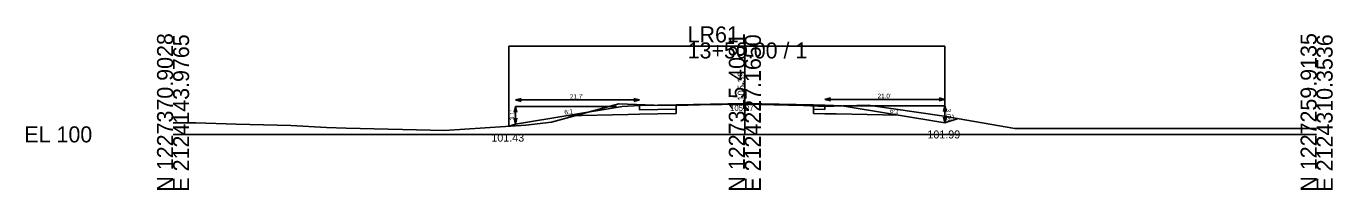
# Model space of a CAD drawing. Extents: x 2126751 to 2128979, y 1225108 to 1234639.
# Drawn here: x 2127750.9 to 2127979.4, y 1228607.5 to 1228636.1 of the extents above; entities that cross this region are included whole.
import ezdxf

# ---------------------------------------------------------------- set-up
doc = ezdxf.new("R2010")
doc.units = 0
for name, color, linetype in [('XS_CELL', 7, 'Continuous'), ('XS_M_DITCH', 7, 'Continuous'), ('XS_P_FINISHED_GRADE', 7, 'Continuous'), ('XS_P_FINISHED_GRADE_ELEV_TX', 7, 'Continuous'), ('XS_P_SUBGRADE_GRANULAR', 7, 'Continuous'), ('XS_P_SUBGRADE_LEVELING', 7, 'Continuous'), ('XS_P_SUBGRADE_PAVEMENT', 7, 'Continuous'), ('XS_P_TX_CLEARZONE', 7, 'Continuous'), ('XS_P_TX_DCH', 7, 'Continuous'), ('XS_P_TX_FS_BS', 7, 'Continuous'), ('XS_X_GROUND', 7, 'Continuous'), ('XS_X_GROUND_TX', 7, 'Continuous')]:
    doc.layers.add(name, color=color, linetype=linetype)

msp = doc.modelspace()

# ---------------------------------------------------------------- linework, layer by layer
at = {"layer": 'XS_CELL'}
for p, q in [((2127876.61, 1228617.21), (2127876.61, 1228633.28)), ((2127776.61, 1228617.21), (2127876.61, 1228617.21)), ((2127876.61, 1228617.21), (2127976.61, 1228617.21))]:
    msp.add_line(p, q, dxfattribs=at)
at = {"layer": 'XS_M_DITCH'}
for p, q in [((2127835.35, 1228618.64), (2127835.35, 1228632.6)), ((2127835.35, 1228632.6), (2127911.61, 1228632.6)), ((2127911.61, 1228632.6), (2127911.61, 1228619.2))]:
    msp.add_line(p, q, dxfattribs=at)
at = {"layer": 'XS_P_FINISHED_GRADE'}
for p, q in [((2127855.16, 1228622.11), (2127836.51, 1228619.02)), ((2127858.18, 1228622.23), (2127855.16, 1228622.11)), ((2127864.61, 1228622.36), (2127858.18, 1228622.23)), ((2127864.61, 1228622.36), (2127876.61, 1228622.6)), ((2127876.61, 1228622.6), (2127888.61, 1228622.36)), ((2127888.61, 1228622.36), (2127890.61, 1228622.32)), ((2127890.61, 1228622.32), (2127893.61, 1228622.2)), ((2127893.61, 1228622.2), (2127911.61, 1228619.2)), ((2127836.51, 1228619.02), (2127835.35, 1228618.64)), ((2127911.61, 1228619.2), (2127913.91, 1228619.97))]:
    msp.add_line(p, q, dxfattribs=at)
at = {"layer": 'XS_P_SUBGRADE_GRANULAR'}
for p, q in [((2127864.61, 1228620.86), (2127864.61, 1228621.61)), ((2127888.61, 1228620.86), (2127888.61, 1228621.61)), ((2127856.18, 1228620.69), (2127845.28, 1228620.47)), ((2127858.18, 1228620.73), (2127856.18, 1228620.69)), ((2127864.61, 1228620.86), (2127858.18, 1228620.73)), ((2127888.61, 1228620.86), (2127890.61, 1228620.82)), ((2127890.61, 1228620.82), (2127892.61, 1228620.78)), ((2127892.61, 1228620.78), (2127903.43, 1228620.56))]:
    msp.add_line(p, q, dxfattribs=at)
at = {"layer": 'XS_P_SUBGRADE_LEVELING'}
for p, q in [((2127864.61, 1228622.28), (2127868.79, 1228622.36)), ((2127864.61, 1228622.36), (2127864.61, 1228622.28)), ((2127868.79, 1228622.36), (2127876.46, 1228622.48)), ((2127876.46, 1228622.48), (2127886.84, 1228622.25)), ((2127886.84, 1228622.25), (2127888.61, 1228622.18)), ((2127888.61, 1228622.36), (2127888.61, 1228622.18))]:
    msp.add_line(p, q, dxfattribs=at)
at = {"layer": 'XS_P_SUBGRADE_PAVEMENT'}
for p, q in [((2127858.18, 1228621.48), (2127858.18, 1228622.23)), ((2127864.61, 1228621.61), (2127858.18, 1228621.48)), ((2127864.61, 1228621.61), (2127864.61, 1228622.28)), ((2127888.61, 1228621.61), (2127888.61, 1228622.18)), ((2127888.61, 1228621.61), (2127890.61, 1228621.57)), ((2127890.61, 1228621.57), (2127890.61, 1228622.32))]:
    msp.add_line(p, q, dxfattribs=at)
at = {"layer": 'XS_P_TX_CLEARZONE'}
for p, q in [((2127836.51, 1228623.23), (2127837.51, 1228623.48)), ((2127858.18, 1228623.23), (2127857.17, 1228623.48)), ((2127890.61, 1228623.32), (2127891.61, 1228623.57)), ((2127890.61, 1228623.32), (2127891.61, 1228623.07)), ((2127890.61, 1228623.32), (2127911.61, 1228623.32)), ((2127911.61, 1228623.32), (2127910.61, 1228623.57)), ((2127911.61, 1228623.32), (2127910.61, 1228623.07)), ((2127836.51, 1228622.11), (2127836.26, 1228621.11)), ((2127836.51, 1228623.23), (2127837.51, 1228622.98)), ((2127858.18, 1228623.23), (2127836.51, 1228623.23)), ((2127836.51, 1228622.11), (2127836.76, 1228621.11)), ((2127836.51, 1228622.11), (2127836.51, 1228619.02)), ((2127854.16, 1228622.11), (2127836.51, 1228622.11)), ((2127858.18, 1228623.23), (2127857.17, 1228622.98)), ((2127894.61, 1228622.2), (2127911.61, 1228622.2)), ((2127911.61, 1228622.2), (2127911.36, 1228621.2)), ((2127911.61, 1228622.2), (2127911.61, 1228619.2)), ((2127911.61, 1228622.2), (2127911.86, 1228621.2)), ((2127836.51, 1228619.02), (2127836.26, 1228620.02)), ((2127836.51, 1228619.02), (2127836.76, 1228620.02)), ((2127911.61, 1228619.2), (2127911.36, 1228620.2)), ((2127911.61, 1228619.2), (2127911.86, 1228620.2))]:
    msp.add_line(p, q, dxfattribs=at)
at = {"layer": 'XS_X_GROUND'}
for p, q in [((2127842.77, 1228619.32), (2127853.71, 1228622.34)), ((2127853.71, 1228622.34), (2127854.59, 1228622.57)), ((2127854.59, 1228622.57), (2127862.25, 1228622.23)), ((2127862.25, 1228622.23), (2127868.79, 1228622.36)), ((2127868.79, 1228622.36), (2127876.46, 1228622.48)), ((2127876.46, 1228622.48), (2127886.84, 1228622.25)), ((2127886.84, 1228622.25), (2127890.59, 1228622.1)), ((2127890.59, 1228622.1), (2127893.82, 1228622.2)), ((2127893.82, 1228622.2), (2127894.24, 1228622.21)), ((2127894.24, 1228622.21), (2127898.15, 1228622.3)), ((2127898.15, 1228622.3), (2127911.08, 1228620.45)), ((2127776.61, 1228619.25), (2127780.6, 1228619.24)), ((2127780.6, 1228619.24), (2127787.67, 1228618.99)), ((2127787.67, 1228618.99), (2127797.19, 1228618.76)), ((2127797.19, 1228618.76), (2127803.44, 1228618.44)), ((2127824.1, 1228617.88), (2127838.33, 1228618.84)), ((2127838.33, 1228618.84), (2127842.77, 1228619.32)), ((2127911.08, 1228620.45), (2127923.84, 1228618.26)), ((2127803.44, 1228618.44), (2127806.87, 1228618.28)), ((2127806.87, 1228618.28), (2127824.1, 1228617.88)), ((2127923.84, 1228618.26), (2127958.91, 1228618.26)), ((2127958.91, 1228618.26), (2127976.61, 1228618.25))]:
    msp.add_line(p, q, dxfattribs=at)

# ---------------------------------------------------------------- texts
at = {"layer": 'XS_CELL'}
for s, p in [('N 1227370.9028', (2127776.61, 1228607.21)), ('N 1227315.4081', (2127876.61, 1228607.21)), ('N 1227259.9135', (2127976.61, 1228607.21)), ('E 2124143.9765', (2127779.41, 1228607.21)), ('E 2124227.1650', (2127879.41, 1228607.21)), ('E 2124310.3536', (2127979.41, 1228607.21))]:
    msp.add_text(s, height=2.8, rotation=90, dxfattribs=at).set_placement(p)
for s, p in [('LR61', (2127866.61, 1228633.28)), ('13+50.00 / 1', (2127866.61, 1228630.48)), ('EL 100', (2127750.61, 1228615.81))]:
    msp.add_text(s, height=2.8, dxfattribs=at).set_placement(p)
at = {"layer": 'XS_P_FINISHED_GRADE_ELEV_TX'}
msp.add_text(' 105.39', height=1.25, rotation=90, dxfattribs=at).set_placement((2127876.61, 1228622.6))
at = {"layer": 'XS_P_TX_CLEARZONE'}
for s, p in [("21.7'", (2127846.03, 1228623.43)), ("21.0'", (2127899.82, 1228623.52))]:
    msp.add_text(s, height=0.8, dxfattribs=at).set_placement(p)
for s, rotation, p in [("3.1'", 90, (2127836.31, 1228619.67)), ("3.0'", 270, (2127911.81, 1228621.72))]:
    msp.add_text(s, height=0.8, rotation=rotation, dxfattribs=at).set_placement(p)
at = {"layer": 'XS_P_TX_DCH'}
for s, p in [('101.43', (2127832.28, 1228615.94)), ('101.99', (2127908.54, 1228616.5))]:
    msp.add_text(s, height=1.4, dxfattribs=at).set_placement(p)
at = {"layer": 'XS_P_TX_FS_BS'}
for s, rotation, p in [('6:1', 9.412, (2127845.11, 1228620.65)), ('6:1', 350.5377, (2127901.95, 1228621.01)), ('3:1', 18.4349, (2127912.05, 1228619.56))]:
    msp.add_text(s, height=0.8, rotation=rotation, dxfattribs=at).set_placement(p)
at = {"layer": 'XS_X_GROUND_TX'}
msp.add_text('105.27', height=1, dxfattribs=at).set_placement((2127874.05, 1228621.31))

doc.saveas('drawing.dxf')
